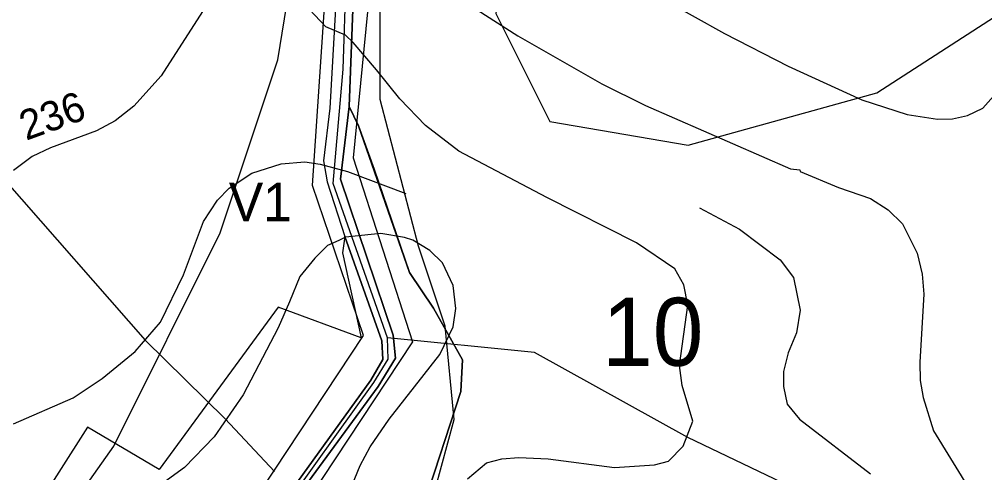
# Model space of a CAD drawing. Extents: x -662500 to -653478, y -1056827 to -1049993.
# Drawn here: x -660014.9 to -659688.8, y -1052767 to -1052613.9 of the extents above; entities that cross this region are included whole.
import ezdxf

# ---------------------------------------------------------------- set-up
doc = ezdxf.new("R2010")
doc.units = 0
for name, color, linetype in [('Vrstva 24', 7, 'Continuous'), ('Vrstva 32', 7, 'Continuous'), ('Vrstva 37', 7, 'Continuous'), ('Vrstva 5', 7, 'Continuous'), ('Vrstva 51', 7, 'Continuous'), ('Vrstva 57', 7, 'Continuous'), ('Vrstva 7', 7, 'Continuous')]:
    doc.layers.add(name, color=color, linetype=linetype)

msp = doc.modelspace()

# ---------------------------------------------------------------- linework, layer by layer
at = {"layer": 'Vrstva 24'}
for points in [[(-660034, -1052954), (-660032, -1052948.5), (-660000, -1052906.38), (-659983, -1052884), (-659923.5, -1052843.5), (-659891.5, -1052807.5), (-659876.5, -1052780.5), (-659868, -1052749), (-659871, -1052717.5), (-659880, -1052690.5), (-659893, -1052641), (-659893, -1052609.5), (-659864.5, -1052533), (-659861.5, -1052506), (-659866.5, -1052474.5), (-659880.5, -1052438.5), (-659901.5, -1052398), (-659927, -1052348.5), (-659940, -1052302)], [(-660132, -1052865), (-660131.5, -1052853), (-660124, -1052843), (-660063.5, -1052832.5), (-660040.5, -1052823.5), (-660028, -1052816), (-660013, -1052800.5), (-660000, -1052782.08), (-659983, -1052758), (-659947, -1052686), (-659927.5, -1052627.5), (-659920, -1052581), (-659923.5, -1052545), (-659933, -1052515), (-659946, -1052493), (-659958.5, -1052479), (-659977, -1052460), (-660000, -1052444.36), (-660002, -1052443), (-660058, -1052408.5), (-660084, -1052396), (-660097, -1052392.5), (-660103, -1052390), (-660138, -1052390)]]:
    msp.add_lwpolyline(points, dxfattribs=at)
at = {"layer": 'Vrstva 32'}
msp.add_lwpolyline([(-659928.36, -1052782.89), (-659895.08, -1052736.55), (-659890.22, -1052728.7), (-659890.47, -1052721.49), (-659908.9, -1052669.32), (-659905.49, -1052630.68), (-659904.41, -1052599.95), (-659898.52, -1052575.7), (-659893.12, -1052552.53), (-659895.67, -1052538.64), (-659900.78, -1052506.64), (-659903.72, -1052495.05), (-659933.15, -1052395.84), (-659942.2, -1052359.57), (-659946.03, -1052344.26)], dxfattribs=at)
at = {"layer": 'Vrstva 37'}
msp.add_lwpolyline([(-659673.12, -1052221.79), (-659730.97, -1052288.96), (-659825.23, -1052254.93), (-659853.32, -1052299.01), (-659834.91, -1052457.14), (-659834.91, -1052490), (-659853.87, -1052611.9), (-659835.65, -1052648.36), (-659788.97, -1052656.33), (-659725.21, -1052638.68), (-659681.94, -1052610.76)], dxfattribs=at)
at = {"layer": 'Vrstva 5'}
for points in [[(-659488.42, -1052589.49), (-659931.7, -1052394.49), (-659912.55, -1052459.34), (-659898.17, -1052506.06), (-659891.78, -1052526.8), (-659889.85, -1052537.24), (-659889.84, -1052553.2), (-659891.97, -1052560.5), (-659899.91, -1052591.56), (-659902.26, -1052610.6), (-659903.49, -1052643.35), (-659900.3, -1052649.88), (-659895.05, -1052664.49), (-659883.07, -1052699.38), (-659874.97, -1052711.4), (-659865.21, -1052728.83), (-659865.78, -1052739.54), (-659878.28, -1052777.87)], [(-660047.2, -1052472.77), (-659979.63, -1052512.63), (-659930.16, -1052541.35), (-659919.38, -1052558.94), (-659924.03, -1052582.63), (-659907.23, -1052585.83), (-659902.96, -1052562.35), (-659919.38, -1052558.94), (-659930.16, -1052541.35), (-659913.07, -1052550.26), (-659898, -1052558.74), (-659905.26, -1052589.98), (-659908.06, -1052610.17), (-659909.98, -1052643.89), (-659912.09, -1052661.63), (-659910.92, -1052668.79), (-659904.94, -1052687.24), (-659905.71, -1052692.7), (-659899.37, -1052721.44), (-659927.4, -1052711.06), (-659967.63, -1052765.86), (-659991.81, -1052751.6), (-660010.37, -1052780.75)], [(-659908.06, -1052610.17), (-659909.98, -1052643.89), (-659912.09, -1052661.63), (-659910.92, -1052668.79), (-659904.94, -1052687.24), (-659892.37, -1052722.42), (-659892.1, -1052728.71), (-659896.18, -1052735.72), (-659929.58, -1052782.17)], [(-659927.06, -1052783.51), (-659893.7, -1052737.91), (-659887.79, -1052728.34), (-659888.54, -1052720.54), (-659906.35, -1052667.8), (-659903.49, -1052643.35), (-659902.26, -1052610.6)], [(-659878.28, -1052777.87), (-659865.78, -1052739.54), (-659865.21, -1052728.83), (-659874.97, -1052711.4), (-659883.07, -1052699.38), (-659900.3, -1052649.88), (-659903.49, -1052643.35), (-659906.35, -1052667.8), (-659888.54, -1052720.54), (-659887.79, -1052728.34), (-659893.7, -1052737.91), (-659927.06, -1052783.51)], [(-659929.58, -1052782.17), (-659896.18, -1052735.72), (-659892.1, -1052728.71), (-659892.37, -1052722.42), (-659904.94, -1052687.24), (-659905.71, -1052692.7), (-659899.37, -1052721.44), (-659927.4, -1052711.06), (-659967.63, -1052765.86), (-659991.81, -1052751.6), (-660010.37, -1052780.75)]]:
    msp.add_lwpolyline(points, dxfattribs=at)
at = {"layer": 'Vrstva 51'}
for points in [[(-660169.13, -1053023.13), (-660110.85, -1052940.58), (-660079.74, -1052916.29), (-659950.2, -1052798.66), (-659898.58, -1052720.65), (-659915.89, -1052669.98), (-659910.89, -1052596.38), (-659900.42, -1052552.71), (-659942.19, -1052387.83), (-659921.6, -1052399.48), (-659893.5, -1052409.43), (-659785.78, -1052462.16), (-659600.37, -1052554.27), (-659621.1, -1052589.25), (-659403.17, -1052709.23)], [(-659408.68, -1052722.85), (-659645.22, -1052595.6), (-659623.64, -1052558.85), (-659899.32, -1052423.28), (-659921, -1052417.16), (-659884.97, -1052552.61), (-659896.01, -1052598.65), (-659902.05, -1052660.61), (-659882, -1052722.78), (-659938.73, -1052808.5), (-660070.07, -1052927.77), (-660099.87, -1052951.04), (-660151.35, -1053023.96)]]:
    msp.add_lwpolyline(points, dxfattribs=at)
at = {"layer": 'Vrstva 57'}
for points in [[(-660144.85, -1052500.62), (-660117.36, -1052556.07), (-660071.54, -1052618.58), (-660019.78, -1052668.15), (-659972.38, -1052722.21), (-659945.35, -1052748.76), (-659928.67, -1052766.62)], [(-659688.88, -1052801.93), (-659719.91, -1052788.18), (-659789.09, -1052755.11), (-659840.79, -1052726.44), (-659890.47, -1052721.49)]]:
    msp.add_lwpolyline(points, dxfattribs=at)
at = {"layer": 'Vrstva 7'}
for p, q in [((-659822.94, -1052592.75), (-659776.6, -1052618.69)), ((-659911.3, -1052616.4), (-659924.69, -1052602.11)), ((-659948.36, -1052603.95), (-659966.92, -1052633)), ((-659860.21, -1052610.61), (-659846.47, -1052619.4)), ((-659904.65, -1052619.18), (-659911.3, -1052616.4)), ((-659776.6, -1052618.69), (-659755.2, -1052629.74)), ((-659902.13, -1052621.7), (-659904.65, -1052619.18)), ((-659894.27, -1052630.89), (-659902.13, -1052621.7)), ((-659846.47, -1052619.4), (-659818.12, -1052635.69)), ((-659886.3, -1052640.67), (-659894.27, -1052630.89)), ((-659755.2, -1052629.74), (-659730.26, -1052641.08)), ((-659966.92, -1052633), (-659976.14, -1052643.2)), ((-659818.12, -1052635.69), (-659803.38, -1052642.92)), ((-659877.61, -1052649.73), (-659886.3, -1052640.67)), ((-659730.26, -1052641.08), (-659714.95, -1052646.04)), ((-659689.44, -1052643.91), (-659685.76, -1052639.8)), ((-659976.14, -1052643.2), (-659982.51, -1052648.16)), ((-659803.38, -1052642.92), (-659754.35, -1052664.32)), ((-659694.55, -1052646.32), (-659689.44, -1052643.91)), ((-659982.51, -1052648.16), (-659988.75, -1052651.56)), ((-659714.95, -1052646.04), (-659704.75, -1052647.6)), ((-659704.75, -1052647.6), (-659699.65, -1052647.46)), ((-659699.65, -1052647.46), (-659694.55, -1052646.32)), ((-659988.75, -1052651.56), (-660004.34, -1052657.23)), ((-659866.38, -1052658.42), (-659877.61, -1052649.73)), ((-660004.34, -1052657.23), (-660010.57, -1052660.21)), ((-660010.57, -1052660.21), (-660016.81, -1052664.89)), ((-659836.69, -1052674.1), (-659866.38, -1052658.42)), ((-659936.31, -1052665.88), (-659926.39, -1052662.62)), ((-659926.39, -1052662.62), (-659918.46, -1052662.05)), ((-659918.46, -1052662.05), (-659913.21, -1052662.76)), ((-659913.21, -1052662.76), (-659904, -1052665.31)), ((-659754.35, -1052664.32), (-659751.23, -1052664.75)), ((-659943.97, -1052670.84), (-659936.31, -1052665.88)), ((-659904, -1052665.31), (-659884.3, -1052672.68)), ((-659751.23, -1052664.75), (-659751.09, -1052665.31)), ((-659751.09, -1052665.31), (-659738.19, -1052670.7)), ((-659947.93, -1052674.95), (-659943.97, -1052670.84)), ((-659738.19, -1052670.7), (-659727.28, -1052674.38)), ((-659806.36, -1052689.4), (-659836.69, -1052674.1)), ((-659727.28, -1052674.38), (-659721.33, -1052678.21)), ((-659952.61, -1052682.18), (-659947.93, -1052674.95)), ((-659785.1, -1052677.5), (-659771.64, -1052684.73)), ((-659721.33, -1052678.21), (-659716.51, -1052682.89)), ((-659959.41, -1052700.17), (-659952.61, -1052682.18)), ((-659716.51, -1052682.89), (-659711.55, -1052692.8)), ((-659904.65, -1052687.39), (-659906.9, -1052688.56)), ((-659892.71, -1052686.16), (-659904.65, -1052687.39)), ((-659884.73, -1052687.56), (-659892.71, -1052686.16)), ((-659771.64, -1052684.73), (-659757.89, -1052695.07)), ((-659910.74, -1052690.26), (-659915.05, -1052694.56)), ((-659906.9, -1052688.56), (-659910.74, -1052690.26)), ((-659881.9, -1052688.41), (-659884.73, -1052687.56)), ((-659876.23, -1052691.95), (-659881.9, -1052688.41)), ((-659793.46, -1052698.19), (-659806.36, -1052689.4)), ((-659871.97, -1052696.06), (-659876.23, -1052691.95)), ((-659711.55, -1052692.8), (-659709.85, -1052699.89)), ((-659915.05, -1052694.56), (-659920.07, -1052700.67)), ((-659868.29, -1052703.72), (-659871.97, -1052696.06)), ((-659757.89, -1052695.07), (-659753.36, -1052701.02)), ((-659967.21, -1052716.19), (-659959.41, -1052700.17)), ((-659790.35, -1052703.57), (-659793.46, -1052698.19)), ((-659709.85, -1052699.89), (-659709.28, -1052706.69)), ((-659920.07, -1052700.67), (-659923.56, -1052709.24)), ((-659867.44, -1052711.51), (-659868.29, -1052703.72)), ((-659789.07, -1052710.38), (-659790.35, -1052703.57)), ((-659753.36, -1052701.02), (-659751.09, -1052712.08)), ((-659709.28, -1052706.69), (-659710.7, -1052729.65)), ((-659923.56, -1052709.24), (-659927.39, -1052718.03)), ((-659868.29, -1052717.75), (-659867.44, -1052711.51)), ((-659791.91, -1052730.78), (-659789.07, -1052710.38)), ((-659751.09, -1052712.08), (-659752.36, -1052719.73)), ((-659975.71, -1052726.11), (-659967.21, -1052716.19)), ((-659927.39, -1052718.03), (-659939.29, -1052740.71)), ((-659872.83, -1052727.1), (-659868.29, -1052717.75)), ((-659752.36, -1052719.73), (-659755.2, -1052726.53)), ((-659986.91, -1052735.18), (-659975.71, -1052726.11)), ((-659755.2, -1052726.53), (-659756.76, -1052732.77)), ((-659889.97, -1052748.93), (-659872.83, -1052727.1)), ((-659710.7, -1052729.65), (-659710.56, -1052735.89)), ((-659790.91, -1052737.59), (-659791.91, -1052730.78)), ((-659756.76, -1052732.77), (-659756.76, -1052737.87)), ((-659996.69, -1052741.7), (-659986.91, -1052735.18)), ((-659710.56, -1052735.89), (-659709.57, -1052741.55)), ((-659787.37, -1052749.63), (-659790.91, -1052737.59)), ((-659756.76, -1052737.87), (-659755.48, -1052743.82)), ((-660016.81, -1052750.48), (-659996.69, -1052741.7)), ((-659939.29, -1052740.71), (-659949.07, -1052754.88)), ((-659709.57, -1052741.55), (-659706.02, -1052752.89)), ((-659755.48, -1052743.82), (-659751.37, -1052748.92)), ((-659896.35, -1052758.28), (-659889.97, -1052748.93)), ((-659751.37, -1052748.92), (-659727.28, -1052767.35)), ((-659790.63, -1052758), (-659787.37, -1052749.63)), ((-659949.07, -1052754.88), (-659959.13, -1052765.22)), ((-659706.02, -1052752.89), (-659693.7, -1052773.02)), ((-659899.75, -1052764.51), (-659896.35, -1052758.28)), ((-659795.59, -1052763.1), (-659790.63, -1052758)), ((-659857.09, -1052763.66), (-659851.89, -1052762.32)), ((-659851.89, -1052762.32), (-659846.18, -1052761.82)), ((-659846.18, -1052761.82), (-659836.26, -1052762.25)), ((-659836.26, -1052762.25), (-659813.87, -1052765.22)), ((-659959.13, -1052765.22), (-659976.28, -1052777.69)), ((-659903.58, -1052773.87), (-659899.75, -1052764.51)), ((-659863.47, -1052769.05), (-659857.09, -1052763.66)), ((-659813.87, -1052765.22), (-659800.27, -1052764.37)), ((-659800.27, -1052764.37), (-659795.59, -1052763.1))]:
    msp.add_line(p, q, dxfattribs=at)

# ---------------------------------------------------------------- texts
at = {"layer": 'Vrstva 32'}
msp.add_text('V1', height=13, rotation=360, dxfattribs=at).set_placement((-659944.08, -1052682.09))
at = {"layer": 'Vrstva 57'}
msp.add_text('10', height=23, dxfattribs=at).set_placement((-659817.99, -1052730.9))
at = {"layer": 'Vrstva 7'}
msp.add_text('236', height=10, rotation=19.984, dxfattribs=at).set_placement((-660012.59, -1052654.91))

doc.saveas('drawing.dxf')
